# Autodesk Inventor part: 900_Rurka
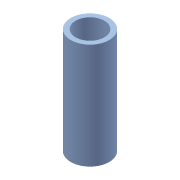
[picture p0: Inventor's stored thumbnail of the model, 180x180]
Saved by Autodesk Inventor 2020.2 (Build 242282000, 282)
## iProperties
Created: 2006-01
Part Number: 900_Rurka
Document SubType Name: Modeling
Designer: F.Stasiak
Density: 1 g/cm^3
Material: Ogólny
Appearance: Niebieski pastelowy
Manager: www.cadconsulting.pl
Company: Fabian Stasiak CAD Consulting
Author: F.Stasiak
Subject: Zbiór ćwiczeń. Autodesk Inventor 2020. Kurs podstawowy
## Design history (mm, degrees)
sketch "Szkic1"
  geometry: C1 r 10 at (0, 0); C2 r 7.5 at (0, 0); 1 further point
  constraints: 2 centre point, 2 coincident
  dimensions: "d0" = 20 diameter of C1; "d1" = 15 diameter of C2
extrude "Wyciągnięcie proste1" new body sketch "Szkic1" stored distance "d2" = 55; taper "d3" = 0 deg
node "Bryła1"
node "Korpusy bryłowe"
node "Korpusy powierzchniowe"
